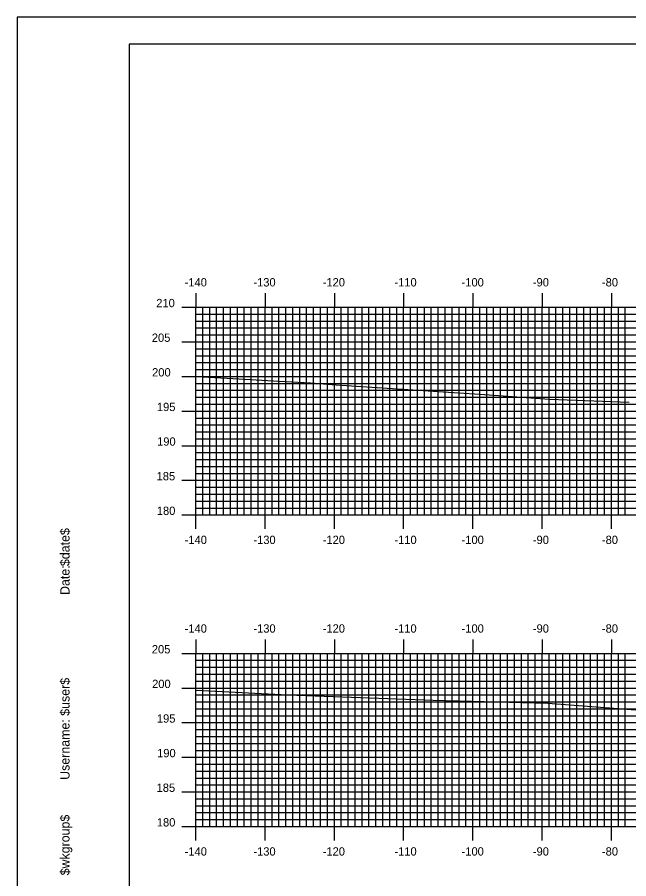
# Model space of a CAD drawing. Extents: x 851300 to 851643, y 366898 to 367118.
# Drawn here: x 851299.7 to 851388, y 366993.9 to 367118.4 of the extents above; entities that cross this region are included whole.
import ezdxf

# ---------------------------------------------------------------- set-up
doc = ezdxf.new("R2010")
doc.units = 0
for name, color, linetype in [('BORDER', 7, 'Continuous'), ('H_V ANNOTATION', 7, 'Continuous'), ('MAJOR', 7, 'Continuous'), ('MINOR', 7, 'Continuous'), ('PLOT BOUNDARY', 7, 'Continuous'), ('S_Roadway_Centerline', 7, 'Continuous')]:
    doc.layers.add(name, color=color, linetype=linetype)

msp = doc.modelspace()

# ---------------------------------------------------------------- linework, layer by layer
at = {"layer": 'BORDER'}
msp.add_lwpolyline([(851315.9, 366904.47), (851635.9, 366904.47), (851635.9, 367114.47), (851315.9, 367114.47)], close=True, dxfattribs=at)
at = {"layer": 'MAJOR'}
for p, q in [((851325.5, 367078.48), (851325.5, 367076.47)), ((851335.5, 367078.48), (851335.5, 367076.47)), ((851345.5, 367078.48), (851345.5, 367076.47)), ((851355.5, 367078.48), (851355.5, 367076.47)), ((851365.5, 367078.48), (851365.5, 367076.47)), ((851375.5, 367078.48), (851375.5, 367076.47)), ((851385.5, 367078.48), (851385.5, 367076.47)), ((851323.5, 367076.47), (851325.5, 367076.47)), ((851325.5, 367076.47), (851605.5, 367076.47)), ((851325.5, 367046.47), (851325.5, 367076.47)), ((851325.5, 367046.47), (851325.5, 367076.47)), ((851325.5, 367076.47), (851605.5, 367076.47)), ((851335.5, 367046.47), (851335.5, 367076.47)), ((851345.5, 367046.47), (851345.5, 367076.47)), ((851355.5, 367046.47), (851355.5, 367076.47)), ((851365.5, 367046.47), (851365.5, 367076.47)), ((851375.5, 367046.47), (851375.5, 367076.47)), ((851385.5, 367046.47), (851385.5, 367076.47)), ((851323.5, 367071.47), (851325.5, 367071.47)), ((851325.5, 367071.47), (851605.5, 367071.47)), ((851323.5, 367066.47), (851325.5, 367066.47)), ((851325.5, 367066.47), (851605.5, 367066.47)), ((851323.5, 367061.47), (851325.5, 367061.47)), ((851325.5, 367061.47), (851605.5, 367061.47)), ((851323.5, 367056.47), (851325.5, 367056.47)), ((851325.5, 367056.47), (851605.5, 367056.47)), ((851323.5, 367051.47), (851325.5, 367051.47)), ((851325.5, 367051.47), (851605.5, 367051.47)), ((851323.5, 367046.47), (851325.5, 367046.47)), ((851325.5, 367046.47), (851605.5, 367046.47)), ((851325.5, 367046.47), (851605.5, 367046.47)), ((851325.5, 367044.47), (851325.5, 367046.47)), ((851335.5, 367044.47), (851335.5, 367046.47)), ((851345.5, 367044.47), (851345.5, 367046.47)), ((851355.5, 367044.47), (851355.5, 367046.47)), ((851365.5, 367044.47), (851365.5, 367046.47)), ((851375.5, 367044.47), (851375.5, 367046.47)), ((851385.5, 367044.47), (851385.5, 367046.47)), ((851325.5, 367028.48), (851325.5, 367026.47)), ((851335.5, 367028.48), (851335.5, 367026.47)), ((851345.5, 367028.48), (851345.5, 367026.47)), ((851355.5, 367028.48), (851355.5, 367026.47)), ((851365.5, 367028.48), (851365.5, 367026.47)), ((851375.5, 367028.48), (851375.5, 367026.47)), ((851385.5, 367028.48), (851385.5, 367026.47)), ((851323.5, 367026.47), (851325.5, 367026.47)), ((851325.5, 367026.47), (851605.5, 367026.47)), ((851325.5, 367001.47), (851325.5, 367026.47)), ((851325.5, 367001.47), (851325.5, 367026.47)), ((851325.5, 367026.47), (851605.5, 367026.47)), ((851335.5, 367001.47), (851335.5, 367026.47)), ((851345.5, 367001.47), (851345.5, 367026.47)), ((851355.5, 367001.47), (851355.5, 367026.47)), ((851365.5, 367001.47), (851365.5, 367026.47)), ((851375.5, 367001.47), (851375.5, 367026.47)), ((851385.5, 367001.47), (851385.5, 367026.47)), ((851323.5, 367021.47), (851325.5, 367021.47)), ((851325.5, 367021.47), (851605.5, 367021.47)), ((851323.5, 367016.47), (851325.5, 367016.47)), ((851325.5, 367016.47), (851605.5, 367016.47)), ((851323.5, 367011.47), (851325.5, 367011.47)), ((851325.5, 367011.47), (851605.5, 367011.47)), ((851323.5, 367006.47), (851325.5, 367006.47)), ((851325.5, 367006.47), (851605.5, 367006.47)), ((851323.5, 367001.47), (851325.5, 367001.47)), ((851325.5, 367001.47), (851605.5, 367001.47)), ((851325.5, 367001.47), (851605.5, 367001.47)), ((851325.5, 366999.47), (851325.5, 367001.47)), ((851335.5, 366999.47), (851335.5, 367001.47)), ((851345.5, 366999.47), (851345.5, 367001.47)), ((851355.5, 366999.47), (851355.5, 367001.47)), ((851365.5, 366999.47), (851365.5, 367001.47)), ((851375.5, 366999.47), (851375.5, 367001.47)), ((851385.5, 366999.47), (851385.5, 367001.47))]:
    msp.add_line(p, q, dxfattribs=at)
at = {"layer": 'MINOR'}
for p, q in [((851326.5, 367046.47), (851326.5, 367076.47)), ((851327.5, 367046.47), (851327.5, 367076.47)), ((851328.5, 367046.47), (851328.5, 367076.47)), ((851329.5, 367046.47), (851329.5, 367076.47)), ((851330.5, 367046.47), (851330.5, 367076.47)), ((851331.5, 367046.47), (851331.5, 367076.47)), ((851332.5, 367046.47), (851332.5, 367076.47)), ((851333.5, 367046.47), (851333.5, 367076.47)), ((851334.5, 367046.47), (851334.5, 367076.47)), ((851336.5, 367046.47), (851336.5, 367076.47)), ((851337.5, 367046.47), (851337.5, 367076.47)), ((851338.5, 367046.47), (851338.5, 367076.47)), ((851339.5, 367046.47), (851339.5, 367076.47)), ((851340.5, 367046.47), (851340.5, 367076.47)), ((851341.5, 367046.47), (851341.5, 367076.47)), ((851342.5, 367046.47), (851342.5, 367076.47)), ((851343.5, 367046.47), (851343.5, 367076.47)), ((851344.5, 367046.47), (851344.5, 367076.47)), ((851346.5, 367046.47), (851346.5, 367076.47)), ((851347.5, 367046.47), (851347.5, 367076.47)), ((851348.5, 367046.47), (851348.5, 367076.47)), ((851349.5, 367046.47), (851349.5, 367076.47)), ((851350.5, 367046.47), (851350.5, 367076.47)), ((851351.5, 367046.47), (851351.5, 367076.47)), ((851352.5, 367046.47), (851352.5, 367076.47)), ((851353.5, 367046.47), (851353.5, 367076.47)), ((851354.5, 367046.47), (851354.5, 367076.47)), ((851356.5, 367046.47), (851356.5, 367076.47)), ((851357.5, 367046.47), (851357.5, 367076.47)), ((851358.5, 367046.47), (851358.5, 367076.47)), ((851359.5, 367046.47), (851359.5, 367076.47)), ((851360.5, 367046.47), (851360.5, 367076.47)), ((851361.5, 367046.47), (851361.5, 367076.47)), ((851362.5, 367046.47), (851362.5, 367076.47)), ((851363.5, 367046.47), (851363.5, 367076.47)), ((851364.5, 367046.47), (851364.5, 367076.47)), ((851366.5, 367046.47), (851366.5, 367076.47)), ((851367.5, 367046.47), (851367.5, 367076.47)), ((851368.5, 367046.47), (851368.5, 367076.47)), ((851369.5, 367046.47), (851369.5, 367076.47)), ((851370.5, 367046.47), (851370.5, 367076.47)), ((851371.5, 367046.47), (851371.5, 367076.47)), ((851372.5, 367046.47), (851372.5, 367076.47)), ((851373.5, 367046.47), (851373.5, 367076.47)), ((851374.5, 367046.47), (851374.5, 367076.47)), ((851376.5, 367046.47), (851376.5, 367076.47)), ((851377.5, 367046.47), (851377.5, 367076.47)), ((851378.5, 367046.47), (851378.5, 367076.47)), ((851379.5, 367046.47), (851379.5, 367076.47)), ((851380.5, 367046.47), (851380.5, 367076.47)), ((851381.5, 367046.47), (851381.5, 367076.47)), ((851382.5, 367046.47), (851382.5, 367076.47)), ((851383.5, 367046.47), (851383.5, 367076.47)), ((851384.5, 367046.47), (851384.5, 367076.47)), ((851386.5, 367046.47), (851386.5, 367076.47)), ((851387.5, 367046.47), (851387.5, 367076.47)), ((851325.5, 367075.47), (851605.5, 367075.47)), ((851325.5, 367075.47), (851327.51, 367075.47)), ((851325.5, 367074.47), (851605.5, 367074.47)), ((851325.5, 367074.47), (851327.51, 367074.47)), ((851325.5, 367073.47), (851605.5, 367073.47)), ((851325.5, 367073.47), (851327.51, 367073.47)), ((851325.5, 367072.47), (851605.5, 367072.47)), ((851325.5, 367072.47), (851327.51, 367072.47)), ((851325.5, 367070.47), (851605.5, 367070.47)), ((851325.5, 367070.47), (851327.51, 367070.47)), ((851325.5, 367069.47), (851605.5, 367069.47)), ((851325.5, 367069.47), (851327.51, 367069.47)), ((851325.5, 367068.47), (851605.5, 367068.47)), ((851325.5, 367068.47), (851327.51, 367068.47)), ((851325.5, 367067.47), (851605.5, 367067.47)), ((851325.5, 367067.47), (851327.51, 367067.47)), ((851325.5, 367065.47), (851605.5, 367065.47)), ((851325.5, 367065.47), (851327.51, 367065.47)), ((851325.5, 367064.47), (851605.5, 367064.47)), ((851325.5, 367064.47), (851327.51, 367064.47)), ((851325.5, 367063.47), (851605.5, 367063.47)), ((851325.5, 367063.47), (851327.51, 367063.47)), ((851325.5, 367062.47), (851605.5, 367062.47)), ((851325.5, 367062.47), (851327.51, 367062.47)), ((851325.5, 367060.47), (851605.5, 367060.47)), ((851325.5, 367060.47), (851327.51, 367060.47)), ((851325.5, 367059.47), (851605.5, 367059.47)), ((851325.5, 367059.47), (851327.51, 367059.47)), ((851325.5, 367058.47), (851605.5, 367058.47)), ((851325.5, 367058.47), (851327.51, 367058.47)), ((851325.5, 367057.47), (851605.5, 367057.47)), ((851325.5, 367057.47), (851327.51, 367057.47)), ((851325.5, 367055.47), (851605.5, 367055.47)), ((851325.5, 367055.47), (851327.51, 367055.47)), ((851325.5, 367054.47), (851605.5, 367054.47)), ((851325.5, 367054.47), (851327.51, 367054.47)), ((851325.5, 367053.47), (851605.5, 367053.47)), ((851325.5, 367053.47), (851327.51, 367053.47)), ((851325.5, 367052.47), (851605.5, 367052.47)), ((851325.5, 367052.47), (851327.51, 367052.47)), ((851325.5, 367050.47), (851605.5, 367050.47)), ((851325.5, 367050.47), (851327.51, 367050.47)), ((851325.5, 367049.47), (851605.5, 367049.47)), ((851325.5, 367049.47), (851327.51, 367049.47)), ((851325.5, 367048.47), (851605.5, 367048.47)), ((851325.5, 367048.47), (851327.51, 367048.47)), ((851325.5, 367047.47), (851605.5, 367047.47)), ((851325.5, 367047.47), (851327.51, 367047.47)), ((851325.5, 367025.47), (851605.5, 367025.47)), ((851325.5, 367025.47), (851327.51, 367025.47)), ((851326.5, 367001.47), (851326.5, 367026.47)), ((851327.5, 367001.47), (851327.5, 367026.47)), ((851328.5, 367001.47), (851328.5, 367026.47)), ((851329.5, 367001.47), (851329.5, 367026.47)), ((851330.5, 367001.47), (851330.5, 367026.47)), ((851331.5, 367001.47), (851331.5, 367026.47)), ((851332.5, 367001.47), (851332.5, 367026.47)), ((851333.5, 367001.47), (851333.5, 367026.47)), ((851334.5, 367001.47), (851334.5, 367026.47)), ((851336.5, 367001.47), (851336.5, 367026.47)), ((851337.5, 367001.47), (851337.5, 367026.47)), ((851338.5, 367001.47), (851338.5, 367026.47)), ((851339.5, 367001.47), (851339.5, 367026.47)), ((851340.5, 367001.47), (851340.5, 367026.47)), ((851341.5, 367001.47), (851341.5, 367026.47)), ((851342.5, 367001.47), (851342.5, 367026.47)), ((851343.5, 367001.47), (851343.5, 367026.47)), ((851344.5, 367001.47), (851344.5, 367026.47)), ((851346.5, 367001.47), (851346.5, 367026.47)), ((851347.5, 367001.47), (851347.5, 367026.47)), ((851348.5, 367001.47), (851348.5, 367026.47)), ((851349.5, 367001.47), (851349.5, 367026.47)), ((851350.5, 367001.47), (851350.5, 367026.47)), ((851351.5, 367001.47), (851351.5, 367026.47)), ((851352.5, 367001.47), (851352.5, 367026.47)), ((851353.5, 367001.47), (851353.5, 367026.47)), ((851354.5, 367001.47), (851354.5, 367026.47)), ((851356.5, 367001.47), (851356.5, 367026.47)), ((851357.5, 367001.47), (851357.5, 367026.47)), ((851358.5, 367001.47), (851358.5, 367026.47)), ((851359.5, 367001.47), (851359.5, 367026.47)), ((851360.5, 367001.47), (851360.5, 367026.47)), ((851361.5, 367001.47), (851361.5, 367026.47)), ((851362.5, 367001.47), (851362.5, 367026.47)), ((851363.5, 367001.47), (851363.5, 367026.47)), ((851364.5, 367001.47), (851364.5, 367026.47)), ((851366.5, 367001.47), (851366.5, 367026.47)), ((851367.5, 367001.47), (851367.5, 367026.47)), ((851368.5, 367001.47), (851368.5, 367026.47)), ((851369.5, 367001.47), (851369.5, 367026.47)), ((851370.5, 367001.47), (851370.5, 367026.47)), ((851371.5, 367001.47), (851371.5, 367026.47)), ((851372.5, 367001.47), (851372.5, 367026.47)), ((851373.5, 367001.47), (851373.5, 367026.47)), ((851374.5, 367001.47), (851374.5, 367026.47)), ((851376.5, 367001.47), (851376.5, 367026.47)), ((851377.5, 367001.47), (851377.5, 367026.47)), ((851378.5, 367001.47), (851378.5, 367026.47)), ((851379.5, 367001.47), (851379.5, 367026.47)), ((851380.5, 367001.47), (851380.5, 367026.47)), ((851381.5, 367001.47), (851381.5, 367026.47)), ((851382.5, 367001.47), (851382.5, 367026.47)), ((851383.5, 367001.47), (851383.5, 367026.47)), ((851384.5, 367001.47), (851384.5, 367026.47)), ((851386.5, 367001.47), (851386.5, 367026.47)), ((851387.5, 367001.47), (851387.5, 367026.47)), ((851325.5, 367024.47), (851605.5, 367024.47)), ((851325.5, 367024.47), (851327.51, 367024.47)), ((851325.5, 367023.47), (851605.5, 367023.47)), ((851325.5, 367023.47), (851327.51, 367023.47)), ((851325.5, 367022.47), (851605.5, 367022.47)), ((851325.5, 367022.47), (851327.51, 367022.47)), ((851325.5, 367020.47), (851605.5, 367020.47)), ((851325.5, 367020.47), (851327.51, 367020.47)), ((851325.5, 367019.47), (851605.5, 367019.47)), ((851325.5, 367019.47), (851327.51, 367019.47)), ((851325.5, 367018.47), (851605.5, 367018.47)), ((851325.5, 367018.47), (851327.51, 367018.47)), ((851325.5, 367017.47), (851605.5, 367017.47)), ((851325.5, 367017.47), (851327.51, 367017.47)), ((851325.5, 367015.47), (851605.5, 367015.47)), ((851325.5, 367015.47), (851327.51, 367015.47)), ((851325.5, 367014.47), (851605.5, 367014.47)), ((851325.5, 367014.47), (851327.51, 367014.47)), ((851325.5, 367013.47), (851605.5, 367013.47)), ((851325.5, 367013.47), (851327.51, 367013.47)), ((851325.5, 367012.47), (851605.5, 367012.47)), ((851325.5, 367012.47), (851327.51, 367012.47)), ((851325.5, 367010.47), (851605.5, 367010.47)), ((851325.5, 367010.47), (851327.51, 367010.47)), ((851325.5, 367009.47), (851605.5, 367009.47)), ((851325.5, 367009.47), (851327.51, 367009.47)), ((851325.5, 367008.47), (851605.5, 367008.47)), ((851325.5, 367008.47), (851327.51, 367008.47)), ((851325.5, 367007.47), (851605.5, 367007.47)), ((851325.5, 367007.47), (851327.51, 367007.47)), ((851325.5, 367005.47), (851605.5, 367005.47)), ((851325.5, 367005.47), (851327.51, 367005.47)), ((851325.5, 367004.47), (851605.5, 367004.47)), ((851325.5, 367004.47), (851327.51, 367004.47)), ((851325.5, 367003.47), (851605.5, 367003.47)), ((851325.5, 367003.47), (851327.51, 367003.47)), ((851325.5, 367002.47), (851605.5, 367002.47)), ((851325.5, 367002.47), (851327.51, 367002.47))]:
    msp.add_line(p, q, dxfattribs=at)
at = {"layer": 'PLOT BOUNDARY'}
msp.add_lwpolyline([(851299.72, 366898.35), (851639.72, 366898.35), (851639.72, 367118.35), (851299.72, 367118.35)], close=True, dxfattribs=at)
at = {"layer": 'S_Roadway_Centerline'}
for points in [[(851325.5, 367066.48), (851330.02, 367066.21), (851337.51, 367065.78), (851342.07, 367065.54), (851345.75, 367065.27), (851363.49, 367064.09), (851366.5, 367063.89), (851376.55, 367063.17), (851388.04, 367062.74)], [(851325.5, 367021.18), (851338.78, 367020.47), (851359.78, 367019.72), (851376.34, 367019.26), (851390.28, 367018.21)]]:
    msp.add_lwpolyline(points, dxfattribs=at)

# ---------------------------------------------------------------- texts
at = {"layer": 'BORDER'}
for s, p in [('$date$', (851307.27, 367039.08)), ('Date:', (851307.27, 367034.91)), ('$user$', (851307.27, 367017.46)), ('Username:', (851307.27, 367008.21)), ('$wkgroup$', (851307.27, 366994.41))]:
    msp.add_text(s, height=1.339, rotation=90, dxfattribs=at).set_placement(p)
at = {"layer": 'H_V ANNOTATION'}
for s, p in [('-140', (851323.89, 367079.47)), ('-130', (851333.81, 367079.47)), ('-120', (851343.82, 367079.47)), ('-110', (851354.17, 367079.47)), ('-100', (851363.87, 367079.47)), ('-90', (851374.16, 367079.47)), ('-80', (851384.13, 367079.47)), ('210', (851319.79, 367076.47)), ('205', (851319.15, 367071.47)), ('200', (851319.19, 367066.47)), ('195', (851319.88, 367061.47)), ('190', (851319.91, 367056.47)), ('185', (851319.84, 367051.47)), ('180', (851319.87, 367046.47)), ('-140', (851323.89, 367042.27)), ('-130', (851333.81, 367042.27)), ('-120', (851343.82, 367042.27)), ('-110', (851354.17, 367042.27)), ('-100', (851363.87, 367042.27)), ('-90', (851374.16, 367042.27)), ('-80', (851384.13, 367042.27)), ('-140', (851323.89, 367029.47)), ('-130', (851333.81, 367029.47)), ('-120', (851343.82, 367029.47)), ('-110', (851354.17, 367029.47)), ('-100', (851363.87, 367029.47)), ('-90', (851374.16, 367029.47)), ('-80', (851384.13, 367029.47)), ('205', (851319.15, 367026.47)), ('200', (851319.19, 367021.47)), ('195', (851319.88, 367016.47)), ('190', (851319.91, 367011.47)), ('185', (851319.84, 367006.47)), ('180', (851319.87, 367001.47)), ('-140', (851323.89, 366997.27)), ('-130', (851333.81, 366997.27)), ('-120', (851343.82, 366997.27)), ('-110', (851354.17, 366997.27)), ('-100', (851363.87, 366997.27)), ('-90', (851374.16, 366997.27)), ('-80', (851384.13, 366997.27))]:
    msp.add_text(s, height=1.2, dxfattribs=at).set_placement(p)
at = {"layer": 'MAJOR'}
for p in [(851325.5, 367046.47), (851325.5, 367001.47)]:
    msp.add_text('-', height=0.012, dxfattribs=at).set_placement(p)

doc.saveas('drawing.dxf')
